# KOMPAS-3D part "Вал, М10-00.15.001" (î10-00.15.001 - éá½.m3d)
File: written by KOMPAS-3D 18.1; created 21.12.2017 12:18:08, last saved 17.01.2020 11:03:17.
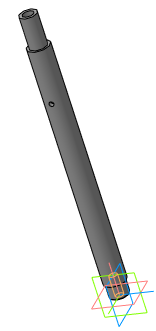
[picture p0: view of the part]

Document properties: Автор: Мирончук; Организация: Мирончук; Полное имя файла: D:\Magna\Магна Ins\Магна ins 10\М10-00.00.000\3Д\М10-00.15.001 - Вал.m3d

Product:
- Part/product: Вал  | designation М10-00.15.001
    Материал: Стержень стеклопластиковый @2~28 (density 2000 kg/m3)
    Масса: 0.395722
    Раздел спецификации: Детали
    Форматы листов документа: A3
    Плотность: 2000
    source file: М10-00.15.001 - Вал.cdw
  - Component: Вал  | designation М10-00.15.001  | Материал: Стержень стеклопластиковый @2~28; Масса: 0.395722; Раздел спецификации: Детали; Форматы листов документа: A3; source file: М10-00.15.001 - Вал.cdw
- Part/product: Вал  | designation М10-00.15.001-0,55кВт
    Масса: 0.395722
    Раздел спецификации: Детали
    Форматы листов документа: 2xA3
    Примечание: @100~)2xA3
    Плотность: 2000
- Part/product: Вал  | designation М10-00.15.001-0,55кВт-375
    Масса: 0.395722
    Раздел спецификации: Детали
    Форматы листов документа: 2xA3
    Примечание: @100~)2xA3
    Плотность: 2000
- Part/product: Вал  | designation М10-00.15.001-0,55кВт-425
    Масса: 0.457297
    Раздел спецификации: Детали
    Форматы листов документа: 2xA3
    Примечание: @100~)2xA3
    Плотность: 2000
- Part/product: Вал  | designation М10-00.15.001-0,55кВт-475
    Масса: 0.518873
    Раздел спецификации: Детали
    Форматы листов документа: 2xA3
    Примечание: @100~)2xA3
    Плотность: 2000
- Part/product: Вал  | designation М10-00.15.001-0,75кВт-1,1кВт
    Материал: Стержень стеклопластиковый @2~28 (density 2000 kg/m3)
    Масса: 0.614757
    Раздел спецификации: Детали
    Форматы листов документа: A3
    Плотность: 2000
- Part/product: Вал  | designation М10-00.15.001-0,75кВт-1,1кВт-375
    Материал: Стержень стеклопластиковый @2~28 (density 2000 kg/m3)
    Масса: 0.614757
    Раздел спецификации: Детали
    Форматы листов документа: A3
    Плотность: 2000
- Part/product: Вал  | designation М10-00.15.001-0,75кВт-1,1кВт-425
    Материал: Стержень стеклопластиковый @2~28 (density 2000 kg/m3)
    Масса: 0.716544
    Раздел спецификации: Детали
    Форматы листов документа: A3
    Плотность: 2000
- Part/product: Вал  | designation М10-00.15.001-0,75кВт-1,1кВт-475
    Материал: Стержень стеклопластиковый @2~28 (density 2000 kg/m3)
    Масса: 0.818332
    Раздел спецификации: Детали
    Форматы листов документа: A3
    Плотность: 2000

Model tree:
1. Эскиз:1
2. Операция вращения:1
     Угол 1 = 360
3. Отверстие:1  (with: Операция вращения:1)
     Глубина выреза = 32; Диаметр отверстия = 14; Угол конуса торца = 118
4. Отверстие:2  (with: Операция вращения:1)  (labels: M10)
     Глубина выреза = 27; Диаметр отверстия = 8.3762; Угол конуса торца = 118
5. M10  (with: Операция вращения:1)  (labels: cil0_24705-2004 coarse)
     Длина резьбы = 25; Шаг резьбы = 1.5; Номинальный диаметр резьбы = 10
6. Фаска:1  (with: Операция вращения:1)
     Угол = 45; Длина 1 = 1; Длина 2 = 1
7. Фаска:2  (with: Отверстие:2)
     Угол = 45; Длина 1 = 1; Длина 2 = 1
8. Эскиз:2  (with: Отверстие:1)
9. Эскиз:3  (with: Операция вращения:1)
10. Отверстие:5  (with: Операция вращения:1)
     Глубина выреза = 6; Диаметр отверстия = 6; Угол конуса торца = 118; Расстояние 2 = -230
11. Фаска:3  (with: Операция вращения:1)  (labels: v536_v439; v536_v438; v536_v437)
     Угол = 45; Длина 1 = 2; Длина 2 = 2

Expressions: 22/2; 24/2; 28/2; 352.5+50; 352.5+100; 352.50+50; 352.50+100
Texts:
  Body Specification ( left align )
  Body Specificaton ( centered )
